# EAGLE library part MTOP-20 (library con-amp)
AMP connector
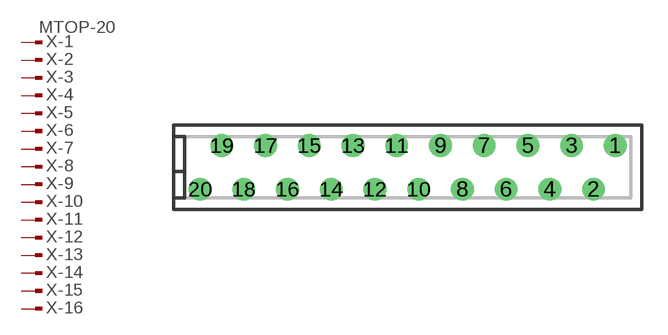
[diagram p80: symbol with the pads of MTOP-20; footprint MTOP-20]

Designator prefix X; gates -1=PIN-MV -2=PIN-M -3=PIN-M -4=PIN-M -5=PIN-M -6=PIN-M -7=PIN-M -8=PIN-M -9=PIN-M -10=PIN-M -11=PIN-M -12=PIN-M -13=PIN-M -14=PIN-M -15=PIN-M -16=PIN-M -17=PIN-M -18=PIN-M -19=PIN-M -20=PIN-M

## MTOP-20 (OC_FARNELL: unknown; OC_NEWARK: unknown)  [MTOP-20]
1  -1:1  pas
2  -2:1  pas
3  -3:1  pas
4  -4:1  pas
5  -5:1  pas
6  -6:1  pas
7  -7:1  pas
8  -8:1  pas
9  -9:1  pas
10  -10:1  pas
11  -11:1  pas
12  -12:1  pas
13  -13:1  pas
14  -14:1  pas
15  -15:1  pas
16  -16:1  pas
17  -17:1  pas
18  -18:1  pas
19  -19:1  pas
20  -20:1  pas

## Footprint MTOP-20 (pad centres in mm)
AMP connector
drill 0.813 round: 1 12.065,1.27; 2 10.795,-1.27; 3 9.525,1.27; 4 8.255,-1.27; 5 6.985,1.27; 6 5.715,-1.27; 7 4.445,1.27; 8 3.175,-1.27; 9 1.905,1.27; 10 0.635,-1.27; 11 -0.635,1.27; 12 -1.905,-1.27; 13 -3.175,1.27; 14 -4.445,-1.27; 15 -5.715,1.27; 16 -6.985,-1.27; 17 -8.255,1.27; 18 -9.525,-1.27; 19 -10.795,1.27; 20 -12.065,-1.27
